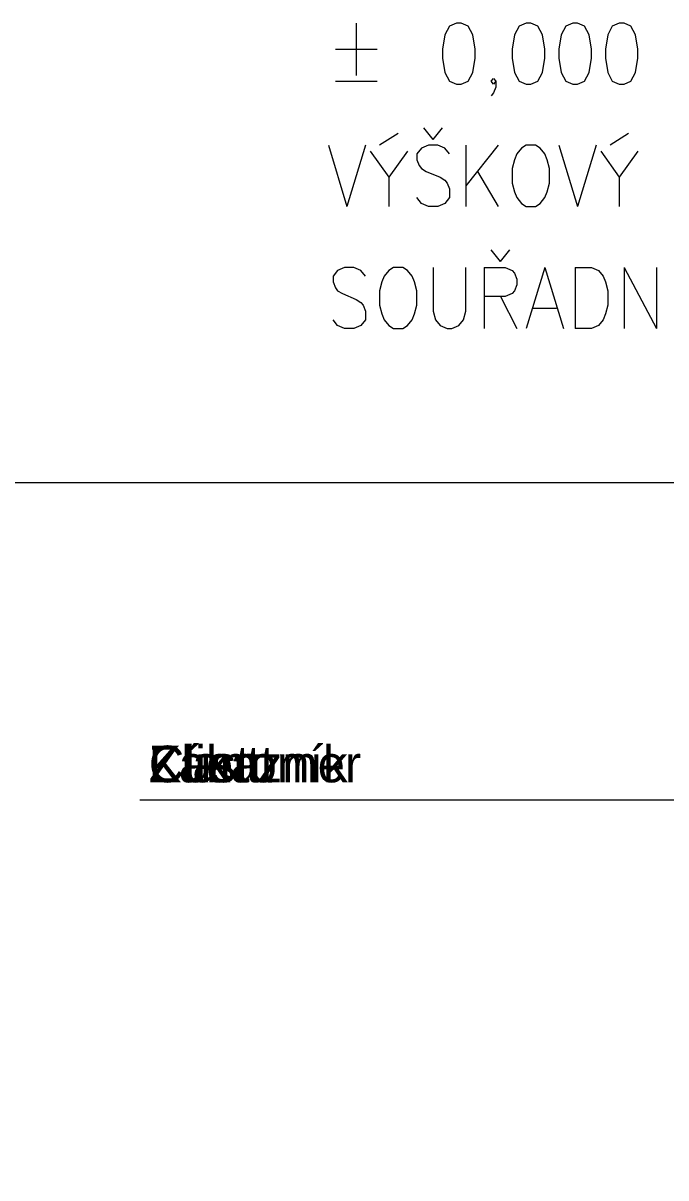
# Model space of a CAD drawing. Extents: x -932963 to -932666, y -737039 to -736000.
# Drawn here: x -932768.96 to -932755.81, y -736904.83 to -736881.2 of the extents above; entities that cross this region are included whole.
import ezdxf

# ---------------------------------------------------------------- set-up
doc = ezdxf.new("R2010")
doc.units = 0
for name, color, linetype in [('Border', 7, 'Continuous'), ('Border_TextCZ', 7, 'Continuous'), ('Border_TextFR', 7, 'Continuous'), ('Border_TextNL', 7, 'Continuous'), ('Border_TextUK', 7, 'Continuous'), ('WA_46_TEXT', 7, 'Continuous')]:
    doc.layers.add(name, color=color, linetype=linetype)

# ---------------------------------------------------------------- blocks, each defined once
blk = doc.blocks.new('A2_v03_CZ')
at = {"layer": 'Border'}
for points in [[(0.384, 0), (0.384, 0.297), (0.594, 0.297)], [(0.393583, 0.284018), (0.584417, 0.284018)]]:
    blk.add_lwpolyline(points, dxfattribs=at)
at = {"layer": 'Border_TextCZ'}
blk.add_text('Zákazník', height=0.0015, dxfattribs=at).set_placement((0.393942, 0.284734))
at = {"layer": 'Border_TextFR'}
blk.add_text('Client', height=0.0015, dxfattribs=at).set_placement((0.393942, 0.284734))
at = {"layer": 'Border_TextNL'}
blk.add_text('Klant', height=0.0015, dxfattribs=at).set_placement((0.393942, 0.284734))
at = {"layer": 'Border_TextUK'}
blk.add_text('Customer', height=0.0015, dxfattribs=at).set_placement((0.393942, 0.284734))

msp = doc.modelspace()

# ---------------------------------------------------------------- linework, layer by layer
at = {"layer": 'WA_46_TEXT'}
for p, q in [((-932762.146, -736881.2), (-932762.146, -736882.271)), ((-932762.146, -736881.2), (-932762.146, -736882.271)), ((-932762.574, -736881.735), (-932761.717, -736881.735)), ((-932762.574, -736881.735), (-932761.717, -736881.735)), ((-932762.574, -736882.39), (-932761.717, -736882.39)), ((-932762.574, -736882.39), (-932761.717, -736882.39)), ((-932760.574, -736883.58), (-932760.765, -736883.342)), ((-932760.574, -736883.58), (-932760.765, -736883.342)), ((-932760.574, -736883.58), (-932760.384, -736883.342)), ((-932760.574, -736883.58), (-932760.384, -736883.342)), ((-932761.288, -736883.461), (-932761.669, -736883.7)), ((-932761.288, -736883.461), (-932761.669, -736883.7)), ((-932756.574, -736883.461), (-932756.955, -736883.7)), ((-932756.574, -736883.461), (-932756.955, -736883.7)), ((-932762.717, -736883.7), (-932762.336, -736884.95)), ((-932762.717, -736883.7), (-932762.336, -736884.95)), ((-932761.955, -736883.7), (-932762.336, -736884.95)), ((-932761.955, -736883.7), (-932762.336, -736884.95)), ((-932761.098, -736883.819), (-932761.479, -736884.354)), ((-932761.098, -736883.819), (-932761.479, -736884.354)), ((-932759.908, -736883.7), (-932759.908, -736884.95)), ((-932759.241, -736883.7), (-932759.908, -736884.533)), ((-932759.908, -736883.7), (-932759.908, -736884.95)), ((-932759.241, -736883.7), (-932759.908, -736884.533)), ((-932758.003, -736883.7), (-932757.622, -736884.95)), ((-932758.003, -736883.7), (-932757.622, -736884.95)), ((-932757.241, -736883.7), (-932757.622, -736884.95)), ((-932757.241, -736883.7), (-932757.622, -736884.95)), ((-932756.384, -736883.819), (-932756.765, -736884.354)), ((-932756.384, -736883.819), (-932756.765, -736884.354)), ((-932759.669, -736884.235), (-932759.241, -736884.95)), ((-932759.669, -736884.235), (-932759.241, -736884.95)), ((-932759.193, -736886.08), (-932759.384, -736885.842)), ((-932759.193, -736886.08), (-932759.384, -736885.842)), ((-932759.193, -736886.08), (-932759.003, -736885.842)), ((-932759.193, -736886.08), (-932759.003, -736885.842)), ((-932758.288, -736886.2), (-932758.669, -736887.45)), ((-932758.288, -736886.2), (-932758.669, -736887.45)), ((-932758.288, -736886.2), (-932757.908, -736887.45)), ((-932758.288, -736886.2), (-932757.908, -736887.45)), ((-932757.669, -736886.2), (-932757.669, -736887.45)), ((-932757.669, -736886.2), (-932757.669, -736887.45)), ((-932756.669, -736886.2), (-932756.669, -736887.45)), ((-932756.669, -736886.2), (-932756.003, -736887.45)), ((-932756.669, -736886.2), (-932756.669, -736887.45)), ((-932756.669, -736886.2), (-932756.003, -736887.45)), ((-932756.003, -736886.2), (-932756.003, -736887.45)), ((-932756.003, -736886.2), (-932756.003, -736887.45)), ((-932759.193, -736886.795), (-932758.86, -736887.45)), ((-932759.193, -736886.795), (-932758.86, -736887.45)), ((-932758.527, -736887.033), (-932758.05, -736887.033)), ((-932758.527, -736887.033), (-932758.05, -736887.033))]:
    msp.add_line(p, q, dxfattribs=at)
for points in [[(-932760.098, -736881.2), (-932760.241, -736881.259), (-932760.336, -736881.438), (-932760.384, -736881.735), (-932760.384, -736881.914), (-932760.336, -736882.211), (-932760.241, -736882.39), (-932760.098, -736882.45), (-932760.003, -736882.45), (-932759.86, -736882.39), (-932759.765, -736882.211), (-932759.717, -736881.914), (-932759.717, -736881.735), (-932759.765, -736881.438), (-932759.86, -736881.259), (-932760.003, -736881.2), (-932760.098, -736881.2)], [(-932760.098, -736881.2), (-932760.241, -736881.259), (-932760.336, -736881.438), (-932760.384, -736881.735), (-932760.384, -736881.914), (-932760.336, -736882.211), (-932760.241, -736882.39), (-932760.098, -736882.45), (-932760.003, -736882.45), (-932759.86, -736882.39), (-932759.765, -736882.211), (-932759.717, -736881.914), (-932759.717, -736881.735), (-932759.765, -736881.438), (-932759.86, -736881.259), (-932760.003, -736881.2), (-932760.098, -736881.2)], [(-932758.669, -736881.2), (-932758.812, -736881.259), (-932758.908, -736881.438), (-932758.955, -736881.735), (-932758.955, -736881.914), (-932758.908, -736882.211), (-932758.812, -736882.39), (-932758.669, -736882.45), (-932758.574, -736882.45), (-932758.431, -736882.39), (-932758.336, -736882.211), (-932758.288, -736881.914), (-932758.288, -736881.735), (-932758.336, -736881.438), (-932758.431, -736881.259), (-932758.574, -736881.2), (-932758.669, -736881.2)], [(-932758.669, -736881.2), (-932758.812, -736881.259), (-932758.908, -736881.438), (-932758.955, -736881.735), (-932758.955, -736881.914), (-932758.908, -736882.211), (-932758.812, -736882.39), (-932758.669, -736882.45), (-932758.574, -736882.45), (-932758.431, -736882.39), (-932758.336, -736882.211), (-932758.288, -736881.914), (-932758.288, -736881.735), (-932758.336, -736881.438), (-932758.431, -736881.259), (-932758.574, -736881.2), (-932758.669, -736881.2)], [(-932757.717, -736881.2), (-932757.86, -736881.259), (-932757.955, -736881.438), (-932758.003, -736881.735), (-932758.003, -736881.914), (-932757.955, -736882.211), (-932757.86, -736882.39), (-932757.717, -736882.45), (-932757.622, -736882.45), (-932757.479, -736882.39), (-932757.384, -736882.211), (-932757.336, -736881.914), (-932757.336, -736881.735), (-932757.384, -736881.438), (-932757.479, -736881.259), (-932757.622, -736881.2), (-932757.717, -736881.2)], [(-932757.717, -736881.2), (-932757.86, -736881.259), (-932757.955, -736881.438), (-932758.003, -736881.735), (-932758.003, -736881.914), (-932757.955, -736882.211), (-932757.86, -736882.39), (-932757.717, -736882.45), (-932757.622, -736882.45), (-932757.479, -736882.39), (-932757.384, -736882.211), (-932757.336, -736881.914), (-932757.336, -736881.735), (-932757.384, -736881.438), (-932757.479, -736881.259), (-932757.622, -736881.2), (-932757.717, -736881.2)], [(-932756.765, -736881.2), (-932756.908, -736881.259), (-932757.003, -736881.438), (-932757.05, -736881.735), (-932757.05, -736881.914), (-932757.003, -736882.211), (-932756.908, -736882.39), (-932756.765, -736882.45), (-932756.669, -736882.45), (-932756.527, -736882.39), (-932756.431, -736882.211), (-932756.384, -736881.914), (-932756.384, -736881.735), (-932756.431, -736881.438), (-932756.527, -736881.259), (-932756.669, -736881.2), (-932756.765, -736881.2)], [(-932756.765, -736881.2), (-932756.908, -736881.259), (-932757.003, -736881.438), (-932757.05, -736881.735), (-932757.05, -736881.914), (-932757.003, -736882.211), (-932756.908, -736882.39), (-932756.765, -736882.45), (-932756.669, -736882.45), (-932756.527, -736882.39), (-932756.431, -736882.211), (-932756.384, -736881.914), (-932756.384, -736881.735), (-932756.431, -736881.438), (-932756.527, -736881.259), (-932756.669, -736881.2), (-932756.765, -736881.2)], [(-932759.288, -736882.39), (-932759.336, -736882.45), (-932759.384, -736882.39), (-932759.336, -736882.33), (-932759.288, -736882.39), (-932759.288, -736882.509), (-932759.336, -736882.628), (-932759.384, -736882.688)], [(-932759.288, -736882.39), (-932759.336, -736882.45), (-932759.384, -736882.39), (-932759.336, -736882.33), (-932759.288, -736882.39), (-932759.288, -736882.509), (-932759.336, -736882.628), (-932759.384, -736882.688)], [(-932761.86, -736883.819), (-932761.479, -736884.354), (-932761.479, -736884.95)], [(-932761.86, -736883.819), (-932761.479, -736884.354), (-932761.479, -736884.95)], [(-932760.241, -736883.878), (-932760.336, -736883.759), (-932760.479, -736883.7), (-932760.669, -736883.7), (-932760.812, -736883.759), (-932760.908, -736883.878), (-932760.908, -736883.997), (-932760.86, -736884.116), (-932760.812, -736884.176), (-932760.717, -736884.235), (-932760.431, -736884.354), (-932760.336, -736884.414), (-932760.288, -736884.473), (-932760.241, -736884.592), (-932760.241, -736884.771), (-932760.336, -736884.89), (-932760.479, -736884.95), (-932760.669, -736884.95), (-932760.812, -736884.89), (-932760.908, -736884.771)], [(-932760.241, -736883.878), (-932760.336, -736883.759), (-932760.479, -736883.7), (-932760.669, -736883.7), (-932760.812, -736883.759), (-932760.908, -736883.878), (-932760.908, -736883.997), (-932760.86, -736884.116), (-932760.812, -736884.176), (-932760.717, -736884.235), (-932760.431, -736884.354), (-932760.336, -736884.414), (-932760.288, -736884.473), (-932760.241, -736884.592), (-932760.241, -736884.771), (-932760.336, -736884.89), (-932760.479, -736884.95), (-932760.669, -736884.95), (-932760.812, -736884.89), (-932760.908, -736884.771)], [(-932758.669, -736883.7), (-932758.765, -736883.759), (-932758.86, -736883.878), (-932758.908, -736883.997), (-932758.955, -736884.176), (-932758.955, -736884.473), (-932758.908, -736884.652), (-932758.86, -736884.771), (-932758.765, -736884.89), (-932758.669, -736884.95), (-932758.479, -736884.95), (-932758.384, -736884.89), (-932758.288, -736884.771), (-932758.241, -736884.652), (-932758.193, -736884.473), (-932758.193, -736884.176), (-932758.241, -736883.997), (-932758.288, -736883.878), (-932758.384, -736883.759), (-932758.479, -736883.7), (-932758.669, -736883.7)], [(-932758.669, -736883.7), (-932758.765, -736883.759), (-932758.86, -736883.878), (-932758.908, -736883.997), (-932758.955, -736884.176), (-932758.955, -736884.473), (-932758.908, -736884.652), (-932758.86, -736884.771), (-932758.765, -736884.89), (-932758.669, -736884.95), (-932758.479, -736884.95), (-932758.384, -736884.89), (-932758.288, -736884.771), (-932758.241, -736884.652), (-932758.193, -736884.473), (-932758.193, -736884.176), (-932758.241, -736883.997), (-932758.288, -736883.878), (-932758.384, -736883.759), (-932758.479, -736883.7), (-932758.669, -736883.7)], [(-932757.146, -736883.819), (-932756.765, -736884.354), (-932756.765, -736884.95)], [(-932757.146, -736883.819), (-932756.765, -736884.354), (-932756.765, -736884.95)], [(-932761.955, -736886.378), (-932762.05, -736886.259), (-932762.193, -736886.2), (-932762.384, -736886.2), (-932762.527, -736886.259), (-932762.622, -736886.378), (-932762.622, -736886.497), (-932762.574, -736886.616), (-932762.527, -736886.676), (-932762.431, -736886.735), (-932762.146, -736886.854), (-932762.05, -736886.914), (-932762.003, -736886.973), (-932761.955, -736887.092), (-932761.955, -736887.271), (-932762.05, -736887.39), (-932762.193, -736887.45), (-932762.384, -736887.45), (-932762.527, -736887.39), (-932762.622, -736887.271)], [(-932761.955, -736886.378), (-932762.05, -736886.259), (-932762.193, -736886.2), (-932762.384, -736886.2), (-932762.527, -736886.259), (-932762.622, -736886.378), (-932762.622, -736886.497), (-932762.574, -736886.616), (-932762.527, -736886.676), (-932762.431, -736886.735), (-932762.146, -736886.854), (-932762.05, -736886.914), (-932762.003, -736886.973), (-932761.955, -736887.092), (-932761.955, -736887.271), (-932762.05, -736887.39), (-932762.193, -736887.45), (-932762.384, -736887.45), (-932762.527, -736887.39), (-932762.622, -736887.271)], [(-932761.384, -736886.2), (-932761.479, -736886.259), (-932761.574, -736886.378), (-932761.622, -736886.497), (-932761.669, -736886.676), (-932761.669, -736886.973), (-932761.622, -736887.152), (-932761.574, -736887.271), (-932761.479, -736887.39), (-932761.384, -736887.45), (-932761.193, -736887.45), (-932761.098, -736887.39), (-932761.003, -736887.271), (-932760.955, -736887.152), (-932760.908, -736886.973), (-932760.908, -736886.676), (-932760.955, -736886.497), (-932761.003, -736886.378), (-932761.098, -736886.259), (-932761.193, -736886.2), (-932761.384, -736886.2)], [(-932761.384, -736886.2), (-932761.479, -736886.259), (-932761.574, -736886.378), (-932761.622, -736886.497), (-932761.669, -736886.676), (-932761.669, -736886.973), (-932761.622, -736887.152), (-932761.574, -736887.271), (-932761.479, -736887.39), (-932761.384, -736887.45), (-932761.193, -736887.45), (-932761.098, -736887.39), (-932761.003, -736887.271), (-932760.955, -736887.152), (-932760.908, -736886.973), (-932760.908, -736886.676), (-932760.955, -736886.497), (-932761.003, -736886.378), (-932761.098, -736886.259), (-932761.193, -736886.2), (-932761.384, -736886.2)], [(-932760.574, -736886.2), (-932760.574, -736887.092), (-932760.527, -736887.271), (-932760.431, -736887.39), (-932760.288, -736887.45), (-932760.193, -736887.45), (-932760.05, -736887.39), (-932759.955, -736887.271), (-932759.908, -736887.092), (-932759.908, -736886.2)], [(-932760.574, -736886.2), (-932760.574, -736887.092), (-932760.527, -736887.271), (-932760.431, -736887.39), (-932760.288, -736887.45), (-932760.193, -736887.45), (-932760.05, -736887.39), (-932759.955, -736887.271), (-932759.908, -736887.092), (-932759.908, -736886.2)], [(-932759.527, -736886.2), (-932759.527, -736887.092), (-932759.527, -736887.45)], [(-932759.527, -736886.2), (-932759.098, -736886.2), (-932758.955, -736886.259), (-932758.908, -736886.319), (-932758.86, -736886.438), (-932758.86, -736886.557), (-932758.908, -736886.676), (-932758.955, -736886.735), (-932759.098, -736886.795), (-932759.527, -736886.795)], [(-932759.527, -736886.2), (-932759.527, -736887.092), (-932759.527, -736887.45)], [(-932759.527, -736886.2), (-932759.098, -736886.2), (-932758.955, -736886.259), (-932758.908, -736886.319), (-932758.86, -736886.438), (-932758.86, -736886.557), (-932758.908, -736886.676), (-932758.955, -736886.735), (-932759.098, -736886.795), (-932759.527, -736886.795)], [(-932757.669, -736886.2), (-932757.336, -736886.2), (-932757.193, -736886.259), (-932757.098, -736886.378), (-932757.05, -736886.497), (-932757.003, -736886.676), (-932757.003, -736886.973), (-932757.05, -736887.152), (-932757.098, -736887.271), (-932757.193, -736887.39), (-932757.336, -736887.45), (-932757.669, -736887.45)], [(-932757.669, -736886.2), (-932757.336, -736886.2), (-932757.193, -736886.259), (-932757.098, -736886.378), (-932757.05, -736886.497), (-932757.003, -736886.676), (-932757.003, -736886.973), (-932757.05, -736887.152), (-932757.098, -736887.271), (-932757.193, -736887.39), (-932757.336, -736887.45), (-932757.669, -736887.45)]]:
    msp.add_lwpolyline(points, dxfattribs=at)

# ---------------------------------------------------------------- block references
at = {"layer": 'Border', "xscale": 499.9999999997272, "yscale": 499.9999999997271, "rotation": -4.538738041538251e-11}
msp.add_blockref('A2_v03_CZ', (-932963.362, -737039.103), dxfattribs=at)

doc.saveas('drawing.dxf')
